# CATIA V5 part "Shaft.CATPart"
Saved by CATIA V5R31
Part number: Part2
Material "Iron": density 7870 kg/m3, Young's modulus 2.11e+11 Pa, Poisson ratio 0.291, thermal expansion 1.21e-05 1/K
Bounding box of the stored display mesh (mm): x -20.121 to 20.121, y 0 to 300, z -20.121 to 20.121
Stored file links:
  D:\PROJECTS\Project 2021\US EDITION\CATIA V5 6R 2021\Resources\Tutorial Files\c19_catia_v5_6r2021_tut\C19_tut_02.CATPart\Shaft.CATPart
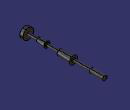
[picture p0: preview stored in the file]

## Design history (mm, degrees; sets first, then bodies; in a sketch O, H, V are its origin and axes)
Body1 (main body), material "Iron"
  Sketch1 on yz-plane, origin (0, 0, 0), H (0, 1, 0), V (0, 0, 1)
    line L1 (0, 0) -> (0, 20.127)
    line L2 (0, 20.127) -> (12.0221, 20.127)
    line L3 (12.0221, 20.127) -> (12.0221, 5.2746)
    point P3 (12.0221, 5.2746)
    line L4 (12.0221, 5.2746) -> (51.1457, 5.2746)
    line L5 (51.1457, 5.2746) -> (51.1457, 8.5349)
    line L6 (51.1457, 8.5349) -> (82.0221, 11.1079)
    line L7 (82.0221, 11.1079) -> (82.0221, 5.2746)
    point P7 (82.0221, 5.2746)
    line L8 (82.0221, 5.2746) -> (132.0221, 5.2746)
    line L9 (132.0221, 5.2746) -> (132.0221, 10.9839)
    line L10 (132.0221, 10.9839) -> (182.0221, 15.1506)
    line L11 (182.0221, 15.1506) -> (182.0221, 5.2746)
    point P11 (182.0221, 5.2746)
    line L12 (182.0221, 5.2746) -> (250, 5.2746)
    line L13 (250, 5.2746) -> (250, 8.5349)
    line L14 (250, 8.5349) -> (300, 8.5349)
    line L15 (300, 8.5349) -> (300, 0)
    point P15 (300, 0)
    axis line L16 (0, 0) -> (300, 0)
    distance L15 L1 = 300
    distance L13 L1 = 250
    distance L11 L7 = 100
    distance L3 L7 = 70
    distance L9 L11 = 50
    vertical: L1 V, L3 V, L5 V, L7 V, L9 V, L11 V, L13 V, L15 V
    horizontal: L2 H, L4 H, L8 H, L12 H, L14 H, L16 H
    coincidence: L6 P3, P7 L4, P11 L4, P15 H
    parallelism: L10 L6
  Shaft1: profile Sketch1, axis Sketch1.L16, angle 360
  Fillet1: radius 2, on edge [face of Shaft1 from Sketch1.L7 | face of Shaft1 from Sketch1.L8]; edge [face of Shaft1 from Sketch1.L4 | face of Shaft1 from Sketch1.L5]; edge [face of Shaft1 from Sketch1.L8 | face of Shaft1 from Sketch1.L9]; edge [face of Shaft1 from Sketch1.L11 | face of Shaft1 from Sketch1.L12]; edge [face of Shaft1 from Sketch1.L12 | face of Shaft1 from Sketch1.L13]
